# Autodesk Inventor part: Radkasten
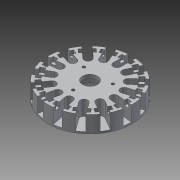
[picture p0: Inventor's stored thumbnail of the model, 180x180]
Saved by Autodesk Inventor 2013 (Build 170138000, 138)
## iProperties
Created: 2012-07
Part Number: Radkasten
Material: Aluminium 6061
Document SubType Name: Modeling
Designer: rYan
Density: 2.71 g/cm^3
Mass: 17.7381 g
Surface Area: 74.0108 cm^2
Volume: 6.54543 cm^3
Author: rYan
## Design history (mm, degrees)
sketch "Skizze1"
  geometry: C1 r 22.5 at (0, 0); 1 further point
  constraints: 1 centre point, 1 coincident
  dimensions: "d0" = 45 diameter of C1
extrude "Extrusion1" new body sketch "Skizze1" distance "d2" = 9; taper "d3" = 0 deg
sketch "Skizze2"
  geometry: L1 (-2, 22.5)-(2, 22.5); L2 (2, 22.5)-(2, 14.5); L3 (-2, 22.5)-(-2, 14.5); L4 (0, 31.5)-(0, -31.5) reference; C1 r 12.5 at (0, 0); C2 r 22.5 at (0, 0) reference; A1 r 2 centre (0, 14.5) between (-2, 14.5) and (2, 14.5); 1 further point
  constraints: 6 end point, 4 tangent, 2 centre point, 2 point on circle, 1 coincident, 1 parallel, 1 perpendicular, 1 other
  dimensions: "d4" = 25 diameter of C1; "d6" = 4 distance between parallel lines of L2 L3
extrude "Extrusion2" cut sketch "Skizze2" distance "d7" = 8; taper "d8" = 0 deg
sketch "Skizze3"
  geometry: L1 (0, 31.5)-(0, -31.5) reference; L2 (-3.25, 20.75)-(3.25, 20.75); L3 (3.25, 18.25)-(-3.25, 18.25); L4 (3.25, 19.5)-(-3.25, 19.5); L5 (3.5, 20.5)-(3.5, 18.5); L6 (-3.5, 20.5)-(-3.5, 18.5); A1 r 22.5 centre (0, 0) between (-2, 22.411) and (2, 22.411) reference; A2 r 22.5 centre (0, 0) between (2, 22.411) and (-2, 22.411); A3 r 0.25 centre (3.25, 20.5) between (3.5, 20.5) and (3.25, 20.75); A4 r 0.25 centre (3.25, 18.5) between (3.25, 18.25) and (3.5, 18.5); A5 r 0.25 centre (-3.25, 20.5) between (-3.25, 20.75) and (-3.5, 20.5); A6 r 0.25 centre (-3.25, 18.5) between (-3.5, 18.5) and (-3.25, 18.25); 2 further points
  constraints: 11 point on circle, 10 end point, 9 tangent, 5 centre point, 2 parallel, 2 symmetric about line, 1 perpendicular, 5 other
  dimensions: "d13" = 6.5 distance of L4.start L4.end; "d14" = 2.5 distance between parallel lines of L3 L2; "d43" = 3 distance from line of L4 point (0, 22.5); "d59" = 0.25 radius of A5; "d60" = 6.5 distance of L3.start L3.end (= d13)
extrude "Extrusion3" cut sketch "Skizze3" distance "d15" = 2.5; taper "d16" = 0 deg
pattern_circular "Runde Anordnung1" dims angle "d10" = 360 deg
sketch "Skizze4"
  geometry: 1 further point
hole "Bohrung1" sketch "Skizze4" at (0, 0) diameter "d17" = 8; stored, may be unused: countersink angle "d21" = 90 deg, drill point angle "d23" = 118 deg; dims "d18" = 6, "d19" = 4, "d20" = 2, "d22" = 8
sketch "Skizze5"
  geometry: 1 further point
hole "Bohrung2" sketch "Skizze5" at (0, 0) diameter "d24" = 22; stored, may be unused: countersink angle "d28" = 90 deg, drill point angle "d30" = 0 deg; dims "d25" = 6, "d26" = 4, "d27" = 2, "d29" = 7
sketch "Skizze6" dims "d31" = 39
  geometry: L1 (0, -31.5)-(0, 31.5) reference; 3 further points
  constraints: 1 coincident, 1 point on line, 1 vertical alignment, 2 other
hole "Bohrung3" sketch "Skizze6" at (0, -19.5) diameter "d33" = 3; stored, may be unused: countersink angle "d37" = 90 deg, drill point angle "d39" = 118 deg; dims "d34" = 6, "d35" = 4, "d36" = 2, "d38" = 4.2
pattern_circular "Runde Anordnung2" dims angle "d41" = 360 deg
sketch "Skizze7"
  geometry: L1 (0, 31.5)-(0, -31.5) reference; L2 (-31.5, 0)-(31.5, 0) reference; 2 further points
  dimensions: "d55" = 9 distance from line of point (0, -9) L2
hole "Bohrung4" sketch "Skizze7" at (0, -9) diameter "d45" = 1.567; stored, may be unused: countersink angle "d49" = 90 deg, drill point angle "d51" = 118 deg; dims "d46" = 6, "d47" = 4, "d48" = 2, "d50" = 5
pattern_circular "Runde Anordnung3" dims angle "d53" = 360 deg
node "Volumenkörper1"
